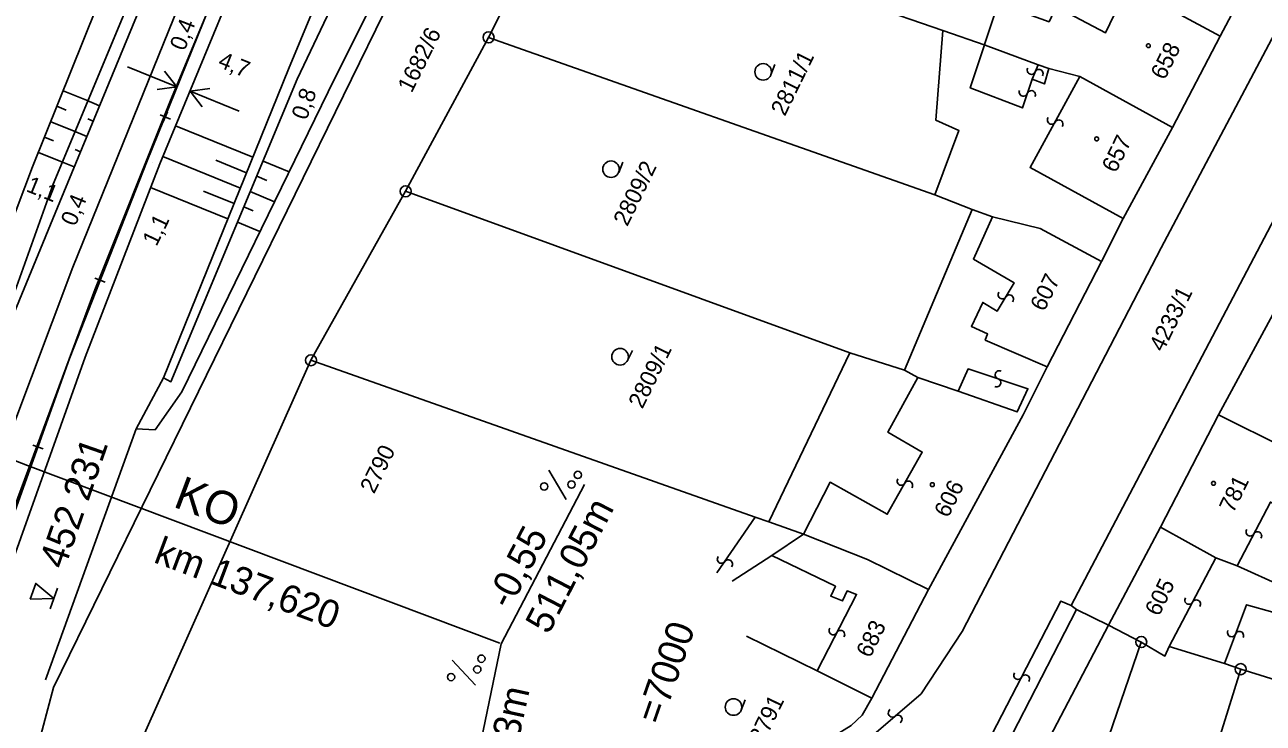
# Model space of a CAD drawing. Extents: x -658910 to -658078, y -1170373 to -1169331.
# Drawn here: x -658393.1 to -658281, y -1169916 to -1169852.8 of the extents above; entities that cross this region are included whole.
import ezdxf

# ---------------------------------------------------------------- set-up
doc = ezdxf.new("R2010")
doc.units = 0
for name, color, linetype in [('Vrstva 1', 7, 'Continuous'), ('Vrstva 10', 7, 'Continuous'), ('Vrstva 11', 7, 'Continuous'), ('Vrstva 12', 7, 'Continuous'), ('Vrstva 38', 7, 'Continuous'), ('Vrstva 39', 7, 'Continuous'), ('Vrstva 6', 7, 'Continuous'), ('Vrstva 8', 7, 'Continuous'), ('Vrstva 9', 7, 'Continuous')]:
    doc.layers.add(name, color=color, linetype=linetype)

msp = doc.modelspace()

# ---------------------------------------------------------------- linework, layer by layer
at = {"layer": 'Vrstva 1'}
msp.add_lwpolyline([(-658344.84, -1169841.441), (-658351.121, -1169853.93), (-658358.621, -1169867.859), (-658367.191, -1169883.15), (-658382.238, -1169916.941), (-658391.102, -1169938.059), (-658392.09, -1169940.24)], dxfattribs=at)
at = {"layer": 'Vrstva 10'}
for p, q in [((-658380.435, -1169856.98), (-658379.327, -1169858.399)), ((-658377.034, -1169860.213), (-658378.131, -1169858.785)), ((-658381.533, -1169865.259), (-658381.533, -1169865.259))]:
    msp.add_line(p, q, dxfattribs=at)
for points in [[(-658362.5, -1169799.992), (-658377.058, -1169834.921), (-658390.526, -1169867.22), (-658399.748, -1169892.989), (-658408.868, -1169924.83), (-658414.693, -1169947.06)], [(-658370.274, -1169800), (-658382.467, -1169825.639), (-658396.121, -1169852.622), (-658406.724, -1169877.812), (-658409.871, -1169887.316), (-658406.874, -1169893.983), (-658404.766, -1169900.848), (-658401.886, -1169890.78), (-658392.378, -1169865.645), (-658379.571, -1169833.72), (-658365.283, -1169800)], [(-658405.482, -1169935.482), (-658403.028, -1169926.019), (-658400.233, -1169916.097), (-658397.067, -1169905.522), (-658393.729, -1169895.606), (-658386.751, -1169876.773), (-658379.972, -1169859.803), (-658372.303, -1169841.365), (-658363.947, -1169821.339), (-658354.813, -1169800)], [(-658399.903, -1169892.997), (-658389.914, -1169868.81), (-658375.827, -1169834.718), (-658360.929, -1169800)], [(-658399.39, -1169913.576), (-658395.005, -1169899.698), (-658389.047, -1169882.978), (-658382.022, -1169865.114), (-658371.363, -1169838.762), (-658362.563, -1169817.838), (-658354.775, -1169800)], [(-658353.23, -1169800), (-658360.347, -1169815.55), (-658370.211, -1169839.636), (-658380.871, -1169865.378), (-658387.629, -1169882.876), (-658398.665, -1169913.79)], [(-658391.204, -1169912.074), (-658383.001, -1169889.369), (-658380.522, -1169884.732), (-658369.219, -1169856.817), (-658355.47, -1169823.699), (-658345.931, -1169800)], [(-658340.746, -1169800), (-658349.362, -1169823.293), (-658357.479, -1169842.49), (-658365.644, -1169858.872), (-658378.881, -1169885.997), (-658381.298, -1169889.443), (-658383.001, -1169889.369)], [(-658380.522, -1169884.732), (-658379.86, -1169885.098), (-658368.425, -1169857.701), (-658352.091, -1169823.348), (-658343.394, -1169800)], [(-658383.777, -1169856.6), (-658379.327, -1169858.399), (-658381.11, -1169858.649)], [(-658373.697, -1169860.622), (-658378.131, -1169858.785), (-658376.346, -1169858.55)], [(-658389.623, -1169858.777), (-658387.511, -1169859.625)], [(-658386.322, -1169860.117), (-658387.511, -1169859.625)], [(-658390.182, -1169860.169), (-658389.344, -1169860.505)], [(-658390.74, -1169861.562), (-658388.666, -1169862.394)], [(-658386.895, -1169861.503), (-658387.372, -1169861.306)], [(-658372.446, -1169864.786), (-658379.451, -1169861.949)], [(-658391.299, -1169862.954), (-658390.476, -1169863.284)], [(-658387.468, -1169862.889), (-658388.666, -1169862.394)], [(-658388.04, -1169864.275), (-658388.521, -1169864.077)], [(-658391.857, -1169864.346), (-658389.82, -1169865.163)], [(-658388.613, -1169865.662), (-658389.82, -1169865.163)], [(-658373.571, -1169867.566), (-658380.599, -1169864.721)], [(-658373.009, -1169866.176), (-658375.788, -1169865.05)], [(-658371.522, -1169865.121), (-658369.172, -1169866.102)], [(-658374.697, -1169870.347), (-658381.696, -1169867.513)], [(-658372.1, -1169866.505), (-658371.192, -1169866.884)], [(-658374.134, -1169868.957), (-658376.903, -1169867.836)], [(-658372.678, -1169867.89), (-658370.49, -1169868.803)], [(-658373.256, -1169869.274), (-658372.413, -1169869.625)], [(-658373.833, -1169870.658), (-658371.808, -1169871.503)]]:
    msp.add_lwpolyline(points, dxfattribs=at)
at = {"layer": 'Vrstva 12'}
for p, q in [((-658380.557, -1169861.586), (-658380.17, -1169860.665)), ((-658380.824, -1169860.932), (-658379.903, -1169861.319)), ((-658386.468, -1169876.36), (-658386.095, -1169875.431)), ((-658386.746, -1169875.709), (-658385.817, -1169876.082)), ((-658392.37, -1169890.822), (-658391.433, -1169891.171)), ((-658392.076, -1169891.465), (-658391.727, -1169890.528))]:
    msp.add_line(p, q, dxfattribs=at)
at = {"layer": 'Vrstva 38'}
for points in [[(-658395.024, -1169891.817), (-658392.843, -1169892.686), (-658350.108, -1169908.755)], [(-658353.245, -1169924.56), (-658349.973, -1169908.805), (-658342.452, -1169894.397)]]:
    msp.add_lwpolyline(points, dxfattribs=at)
at = {"layer": 'Vrstva 39'}
for p, q in [((-658344.082, -1169895.75), (-658345.671, -1169893.099)), ((-658390.779, -1169905.662), (-658390.122, -1169903.773)), ((-658352.309, -1169912.548), (-658354.424, -1169910.294))]:
    msp.add_line(p, q, dxfattribs=at)
msp.add_lwpolyline([(-658392.586, -1169904.769), (-658390.451, -1169904.718), (-658392.093, -1169903.352), (-658392.586, -1169904.769)], dxfattribs=at)
for centre in [(-658343.047, -1169893.531), (-658346.082, -1169894.574), (-658343.612, -1169894.399), (-658351.768, -1169910.16), (-658352.137, -1169911.129), (-658354.513, -1169911.823)]:
    msp.add_circle(centre, 0.331, dxfattribs=at)
at = {"layer": 'Vrstva 6'}
msp.add_lwpolyline([(-658394.353, -1169889.651), (-658388.744, -1169874.733), (-658378.733, -1169850.005), (-658370.721, -1169831.006)], dxfattribs=at)
at = {"layer": 'Vrstva 8'}
for p, q in [((-658353.359, -1169836.99), (-658390.5, -1169912.76)), ((-658351.171, -1169853.93), (-658351.071, -1169853.93)), ((-658351.171, -1169853.93), (-658351.071, -1169853.93)), ((-658358.671, -1169867.859), (-658358.571, -1169867.859)), ((-658358.671, -1169867.859), (-658358.571, -1169867.859)), ((-658367.241, -1169883.15), (-658367.141, -1169883.15)), ((-658367.241, -1169883.15), (-658367.141, -1169883.15)), ((-658292.109, -1169908.65), (-658292.009, -1169908.65)), ((-658292.109, -1169908.65), (-658292.009, -1169908.65)), ((-658283.109, -1169911.109), (-658283.009, -1169911.109)), ((-658283.109, -1169911.109), (-658283.009, -1169911.109)), ((-658390.5, -1169912.76), (-658394.43, -1169927.801))]:
    msp.add_line(p, q, dxfattribs=at)
for points in [[(-658387.949, -1169938.809), (-658387.691, -1169939.66), (-658386.93, -1169940.059), (-658385.551, -1169939.961), (-658348.719, -1169928.68), (-658324.219, -1169920.969), (-658320.5, -1169919.58), (-658316.68, -1169917.379), (-658311.98, -1169913.33), (-658308.27, -1169907.711), (-658290.262, -1169872.99), (-658247.48, -1169792.15)], [(-658241.422, -1169797.309), (-658274.379, -1169859.65), (-658298.41, -1169905.359), (-658299.328, -1169904.949), (-658306.441, -1169918.719), (-658309.219, -1169921.43), (-658312.328, -1169924.01), (-658317.922, -1169927.83), (-658323.578, -1169930.32), (-658329.719, -1169932.26), (-658318.578, -1169935.711), (-658319.199, -1169937.449), (-658321.859, -1169936.67), (-658326.539, -1169935.43), (-658331.32, -1169933.879), (-658341.281, -1169937.379)], [(-658276.289, -1169837.699), (-658282.578, -1169849.371), (-658284.91, -1169853.82), (-658293.27, -1169849.309), (-658295.289, -1169853.51), (-658299.762, -1169851.17), (-658300.398, -1169852.52), (-658305.02, -1169850.871), (-658307.531, -1169858.51), (-658302.801, -1169860.309), (-658301.941, -1169857.699), (-658300.82, -1169858.141), (-658300.43, -1169856.74), (-658297.602, -1169857.48), (-658302.121, -1169865.719), (-658293.68, -1169870.309), (-658289.23, -1169862.09), (-658297.602, -1169857.48)], [(-658310.02, -1169853.309), (-658316.851, -1169850.942)], [(-658313.48, -1169884.039), (-658318.422, -1169882.48), (-658358.621, -1169867.859), (-658351.121, -1169853.93), (-658310.73, -1169868.191)], [(-658301.379, -1169856.42), (-658306.18, -1169854.65), (-658310.02, -1169853.309), (-658310.66, -1169861.41), (-658308.551, -1169862.35), (-658310.73, -1169868.191), (-658307.359, -1169869.51), (-658305.531, -1169870.17), (-658301.199, -1169871.219), (-658295.641, -1169874.211), (-658293.68, -1169870.309)], [(-658289.23, -1169862.09), (-658284.91, -1169853.82)], [(-658300.43, -1169856.74), (-658301.379, -1169856.42), (-658301.941, -1169857.699)], [(-658307.359, -1169869.51), (-658313.48, -1169884.039), (-658312.289, -1169884.711)], [(-658300.559, -1169883.74), (-658306.18, -1169881.33), (-658305.961, -1169880.77), (-658307.422, -1169880.09), (-658306.398, -1169877.92), (-658305.09, -1169878.699), (-658303.559, -1169876.141), (-658307.238, -1169874), (-658305.531, -1169870.17)], [(-658295.641, -1169874.211), (-658300.559, -1169883.74), (-658302.738, -1169888.08), (-658311.301, -1169903.9), (-658316.441, -1169913.73), (-658321.391, -1169911.26), (-658317.82, -1169904.35), (-658318.672, -1169904.02), (-658319.078, -1169904.93), (-658320.148, -1169904.51), (-658319.738, -1169903.6), (-658325.488, -1169900.809), (-658322.629, -1169898.879), (-658320.211, -1169894.199), (-658315.039, -1169897.09), (-658311.871, -1169891.469), (-658314.98, -1169889.66), (-658312.289, -1169884.711), (-658308.629, -1169885.941), (-658307.73, -1169883.93), (-658302.309, -1169885.73), (-658303.281, -1169887.82), (-658308.629, -1169885.941)], [(-658285.078, -1169888.09), (-658279.371, -1169877.57), (-658275.91, -1169879.621), (-658275.75, -1169879.199), (-658268.91, -1169882.891)], [(-658326.98, -1169897.34), (-658367.191, -1169883.15)], [(-658318.422, -1169882.48), (-658325.75, -1169897.77), (-658326.98, -1169897.34), (-658330.448, -1169902.404)], [(-658289.52, -1169909.059), (-658285.301, -1169901.02), (-658290.301, -1169898.25), (-658285.078, -1169888.09), (-658279, -1169891.109), (-658275.449, -1169884.52), (-658269.898, -1169886.691)], [(-658273.66, -1169898.93), (-658277.949, -1169897.25), (-658280.371, -1169895.98), (-658283.379, -1169901.77)], [(-658311.301, -1169903.9), (-658316.82, -1169901.17), (-658322.629, -1169898.879), (-658325.75, -1169897.77)], [(-658295.012, -1169907.121), (-658290.301, -1169898.25)], [(-658329.075, -1169903.157), (-658325.488, -1169900.809)], [(-658279.25, -1169903.621), (-658283.379, -1169901.77), (-658285.301, -1169901.02)], [(-658284.52, -1169910.59), (-658282.539, -1169905.281), (-658280.16, -1169905.941), (-658279.25, -1169903.621), (-658276.68, -1169904.621)], [(-658295.012, -1169907.121), (-658297.91, -1169905.719), (-658298.41, -1169905.359)], [(-658297.91, -1169905.719), (-658312.691, -1169934.43)], [(-658292.059, -1169908.65), (-658295.012, -1169907.121), (-658309.91, -1169935.57)], [(-658327.78, -1169908.12), (-658321.391, -1169911.26)], [(-658283.059, -1169911.109), (-658284.52, -1169910.59), (-658289.52, -1169909.059), (-658289.91, -1169909.92), (-658292.059, -1169908.65), (-658302.352, -1169938.691)], [(-658292.5, -1169941.42), (-658283.059, -1169911.109), (-658279.07, -1169912.35)], [(-658316.441, -1169913.73), (-658317.309, -1169915.26), (-658318.32, -1169916.211), (-658319.961, -1169917.23), (-658322.07, -1169918.49), (-658328.25, -1169920.67), (-658338.93, -1169923.879), (-658347.781, -1169921.33), (-658347.143, -1169920.814)]]:
    msp.add_lwpolyline(points, dxfattribs=at)
for centre in [(-658351.121, -1169853.93), (-658351.121, -1169853.93), (-658358.621, -1169867.859), (-658358.621, -1169867.859), (-658367.191, -1169883.15), (-658367.191, -1169883.15), (-658292.059, -1169908.65), (-658292.059, -1169908.65), (-658283.059, -1169911.109), (-658283.059, -1169911.109)]:
    msp.add_circle(centre, 0.499, dxfattribs=at)
for centre, radius, start, end in [((-658302.003, -1169856.905), 0.376, 149.62146, 335.93259), ((-658301.314, -1169857.208), 0.377, 328.94542, 156.60863), ((-658302.727, -1169858.888), 0.376, 154.80169, 341.11282), ((-658302.013, -1169859.127), 0.377, 334.12564, 161.78886), ((-658300.179, -1169861.415), 0.376, 144.30401, 330.61514), ((-658299.521, -1169861.781), 0.377, 323.62797, 151.29118), ((-658304.64, -1169877.222), 0.376, 142.00232, 328.31346), ((-658303.997, -1169877.614), 0.377, 321.32628, 148.9895), ((-658304.901, -1169884.472), 0.377, 63.96892, 251.63214), ((-658305.142, -1169885.185), 0.376, 244.64496, 70.9561), ((-658313.774, -1169894.092), 0.376, 143.63869, 329.94983), ((-658313.12, -1169894.465), 0.377, 322.96265, 150.62587), ((-658282.202, -1169898.693), 0.376, 145.48293, 331.79406), ((-658281.537, -1169899.045), 0.377, 324.80689, 152.4701), ((-658330.046, -1169901.154), 0.376, 138.62908, 324.94021), ((-658329.427, -1169901.583), 0.377, 317.95304, 145.61625), ((-658287.741, -1169904.86), 0.376, 145.32479, 331.63593), ((-658287.076, -1169905.214), 0.377, 324.64875, 152.31197), ((-658319.934, -1169907.624), 0.376, 145.71859, 332.02972), ((-658319.267, -1169907.973), 0.377, 325.04254, 152.70576), ((-658283.882, -1169907.794), 0.376, 152.52069, 338.83182), ((-658283.178, -1169908.061), 0.377, 331.84464, 159.50786), ((-658303.211, -1169911.653), 0.376, 145.71584, 332.02697), ((-658302.544, -1169912.002), 0.377, 325.03979, 152.70301), ((-658314.57, -1169915.07), 0.376, 123.73129, 310.04242), ((-658314.082, -1169915.644), 0.377, 303.05525, 130.71846)]:
    msp.add_arc(centre, radius, start, end, dxfattribs=at)
at = {"layer": 'Vrstva 9'}
for p, q in [((-658325.575, -1169857.33), (-658325.207, -1169856.401)), ((-658339.345, -1169866.153), (-658338.957, -1169865.232)), ((-658338.538, -1169883.161), (-658338.106, -1169882.26)), ((-658328.26, -1169914.817), (-658327.884, -1169913.891))]:
    msp.add_line(p, q, dxfattribs=at)
for centre, radius in [((-658291.412, -1169854.687), 0.175), ((-658326.273, -1169857.054), 0.75), ((-658296.095, -1169863.119), 0.175), ((-658340.037, -1169865.862), 0.75), ((-658339.215, -1169882.837), 0.75), ((-658310.962, -1169894.411), 0.175), ((-658285.523, -1169894.291), 0.175), ((-658328.955, -1169914.535), 0.75)]:
    msp.add_circle(centre, radius, dxfattribs=at)

# ---------------------------------------------------------------- texts
at = {"layer": 'Vrstva 11'}
for s, rotation, p in [('0,4', 68.55443, (-658378.628, -1169855.232)), ('4,7', 337.96048, (-658375.692, -1169856.565)), ('0,8', 70.39776, (-658367.591, -1169861.494)), ('1,1', 338.1449, (-658393.045, -1169867.836)), ('0,4', 67.55013, (-658388.507, -1169871.102)), ('1,1', 63.95569, (-658381.171, -1169872.914))]:
    msp.add_text(s, height=1.5, rotation=rotation, dxfattribs=at).set_placement(p)
at = {"layer": 'Vrstva 39'}
for s, height, rotation, p in [('452 231', 2.5, 70.82292, (-658389.488, -1169902.16)), ('KO', 3, 339.39308, (-658379.758, -1169896.377)), ('511,05m', 2.5, 62.63968, (-658345.683, -1169908.05)), ('-0,55', 2.5, 62.63968, (-658349.187, -1169905.787)), ('km 137,620', 2.5, 339.39308, (-658381.531, -1169901.402)), ('=7000', 2.5, 70.82292, (-658335.484, -1169916.239)), ('569,83m', 2.5, 77.77125, (-658350.146, -1169925.685))]:
    msp.add_text(s, height=height, rotation=rotation, dxfattribs=at).set_placement(p)
at = {"layer": 'Vrstva 9'}
for s, p in [('1682/6', (-658358.075, -1169859.027)), ('658', (-658289.936, -1169857.868)), ('2811/1', (-658324.309, -1169861.134)), ('657', (-658294.36, -1169866.276)), ('2809/2', (-658338.561, -1169871.109)), ('607', (-658300.838, -1169878.817)), ('4233/1', (-658290.074, -1169882.475)), ('2809/1', (-658337.198, -1169887.625)), ('2790', (-658361.478, -1169895.309)), ('606', (-658309.528, -1169897.488)), ('781', (-658283.738, -1169897.058)), ('605', (-658290.453, -1169906.404)), ('683', (-658316.585, -1169910.172)), ('2791', (-658326.289, -1169917.933))]:
    msp.add_text(s, height=1.5, rotation=63.88515, dxfattribs=at).set_placement(p)

doc.saveas('drawing.dxf')
